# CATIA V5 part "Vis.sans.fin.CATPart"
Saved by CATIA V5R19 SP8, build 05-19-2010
Part number: Vis.sans.fin
Bounding box of the stored display mesh (mm): x -15 to -9, y -13.5 to 3, z -2.853 to 2.853
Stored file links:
  G:\EU_thinkMotion\CFAO_2010\MMS_groupe3\MMS_groupe3\jbonnamy\jbonnamy_cfao\Vis.sans.fin.CATPart
  G:\EU_thinkMotion\CFAO_2010\MMS_groupe3\MMS_groupe3\jbonnamy\jbonnamy_cfao\jbonnamy_suspension.arriere.directionnelle.CATProduct
  G:\EU_thinkMotion\CFAO_2010\MMS_groupe3\MMS_groupe3\jbonnamy\jbonnamy_cfao\Moteur.CATPart
  G:\EU_thinkMotion\CFAO_2010\MMS_groupe3\MMS_groupe3\jbonnamy\jbonnamy_cfao\SKL.general.CATPart
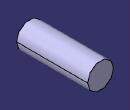
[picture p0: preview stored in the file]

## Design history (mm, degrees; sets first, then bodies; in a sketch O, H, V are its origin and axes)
External parameters (linked from other documents)
  External.Diametre.primitif.vis.sans.fin = 6 mm
  External.Longueur.vis.sans.fin = 16.5 mm
  External.Distance.support.10.centre.pignon = 16 mm
  `External.Distance.centre.pivot.plan moteur` = 13.5 mm
Set1
  Plane1: linked copy from another document
  Point1 "Point.vis.sans.fin": linked copy from another document
Body1 (main body)
  Sketch1 on Plane1, origin (0, -13.5, 0), H (-1, 0, 0), V (0, 0, 1)
    circle A1 centre (12, 0) radius 3
    point P1 (12, 0)
    reference projected point E1 (12, 0) from Point1
    radius A1 = 3 {= External.Diametre.primitif.vis.sans.fin /2}
    distance P1 E1 = 0
  Pad1: profile Sketch1, direction (0, 1, 0), length 16.5 {= External.Longueur.vis.sans.fin}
